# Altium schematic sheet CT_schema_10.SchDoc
size 741 x 377 mm
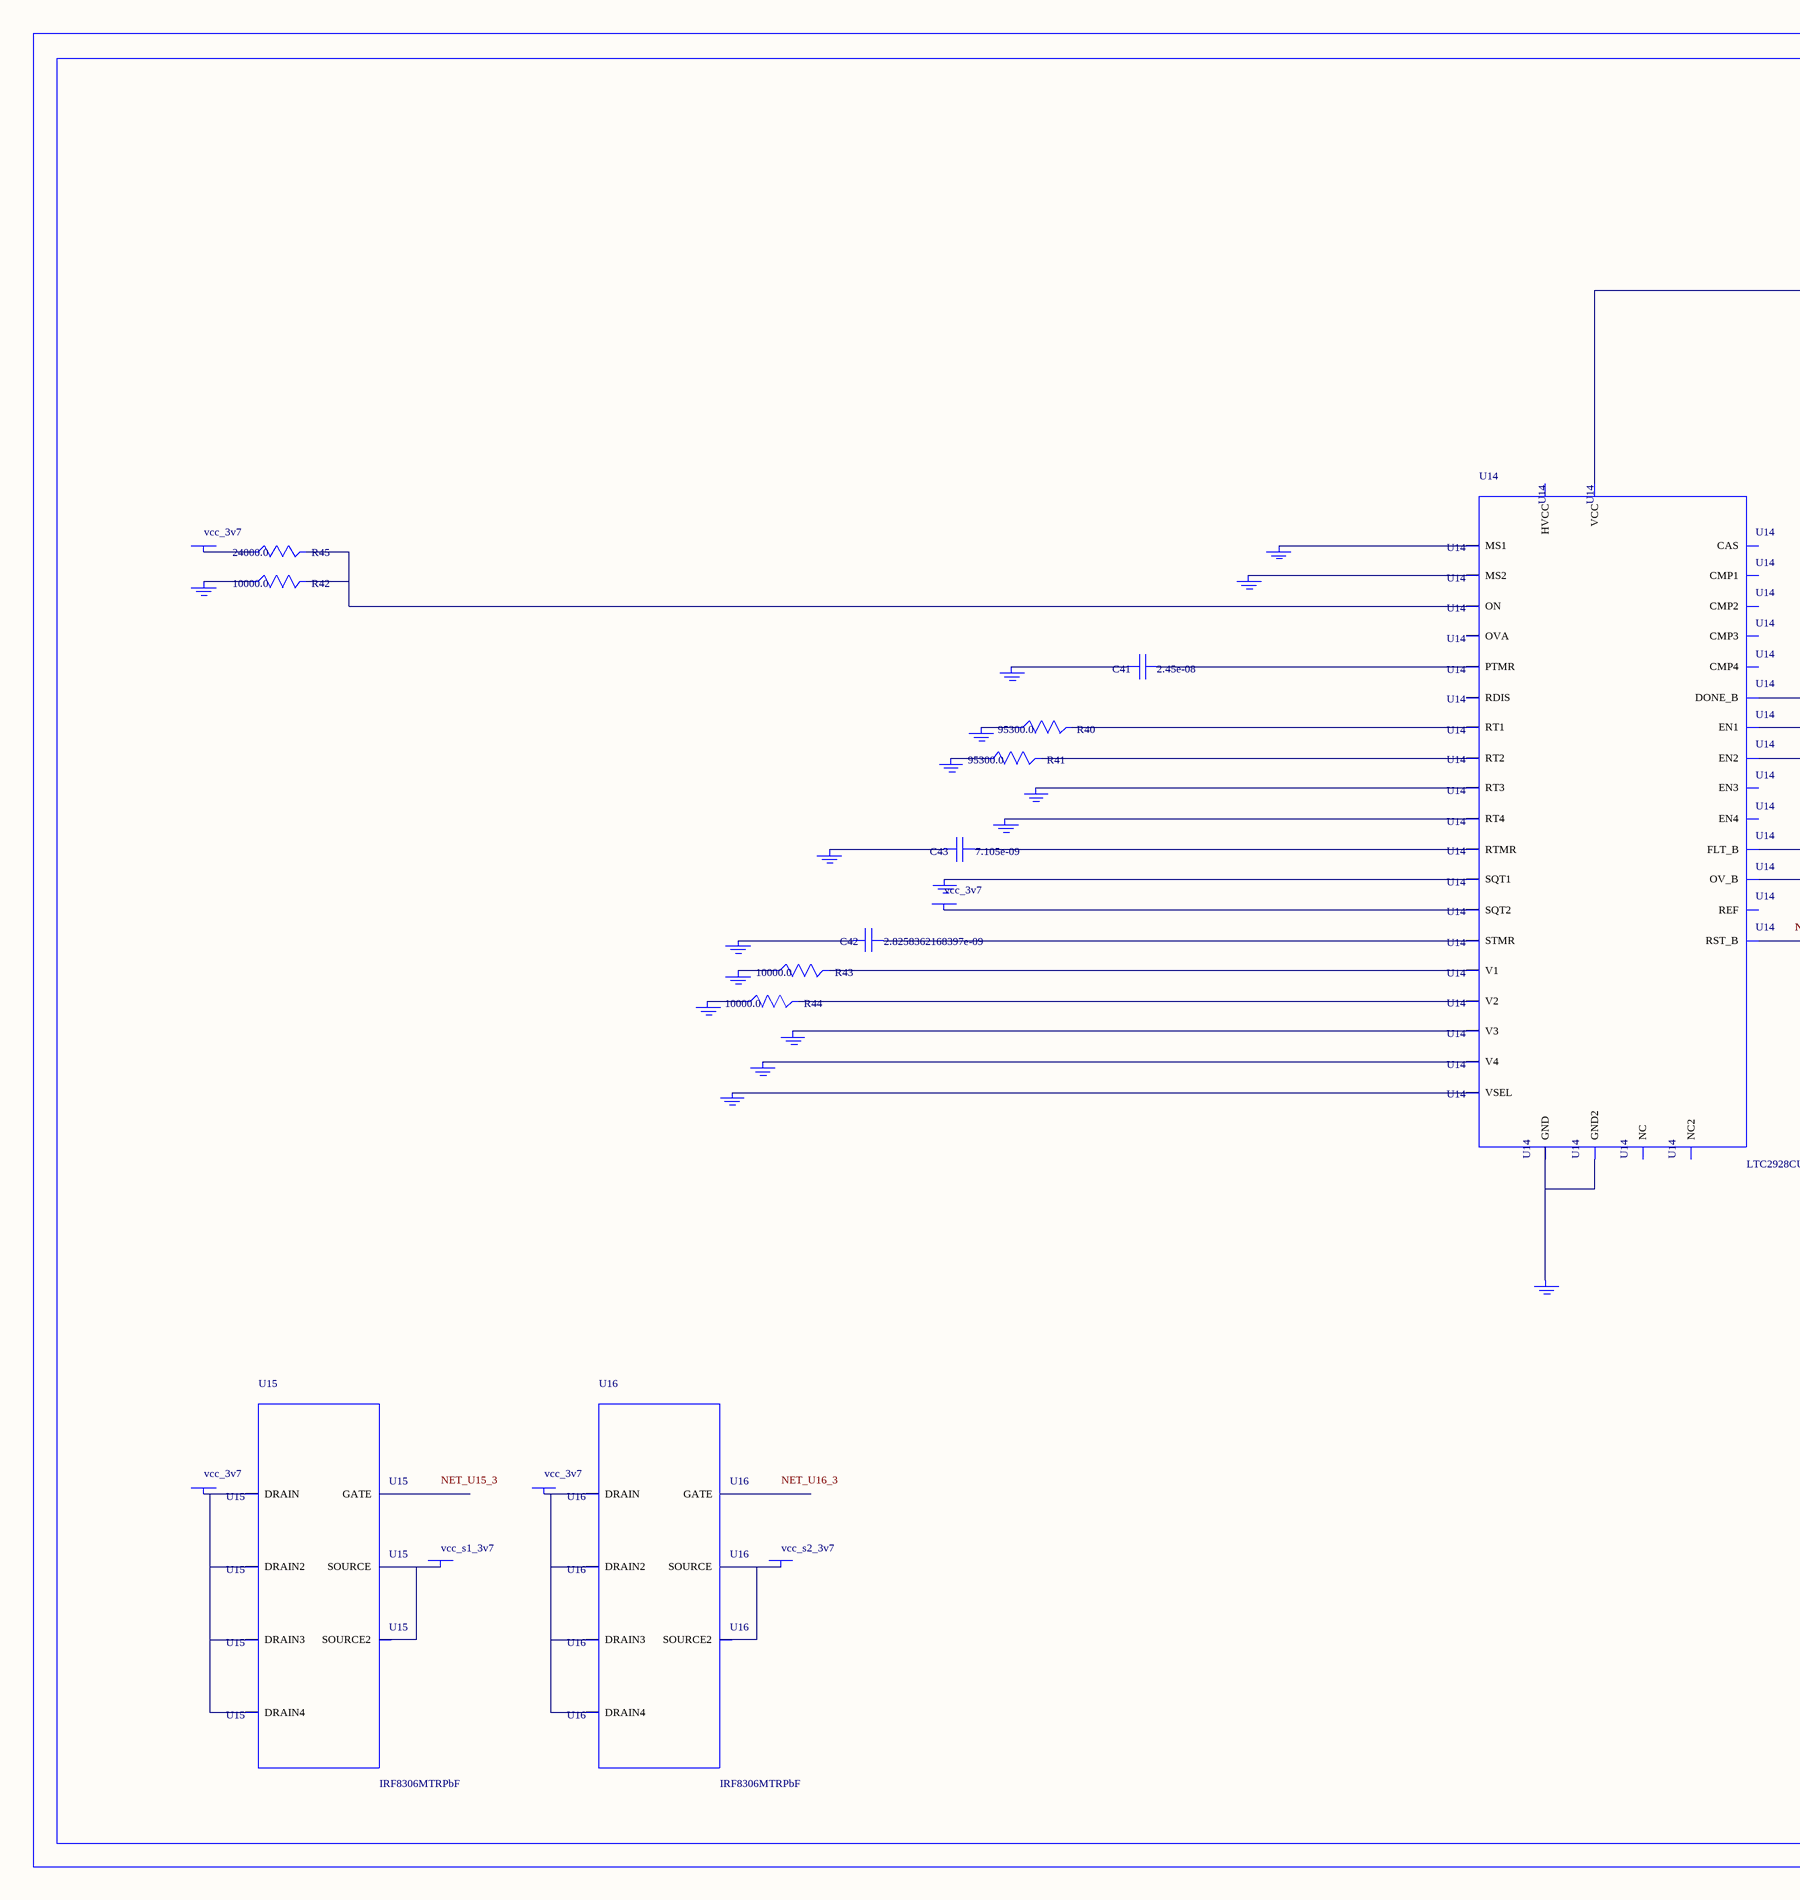
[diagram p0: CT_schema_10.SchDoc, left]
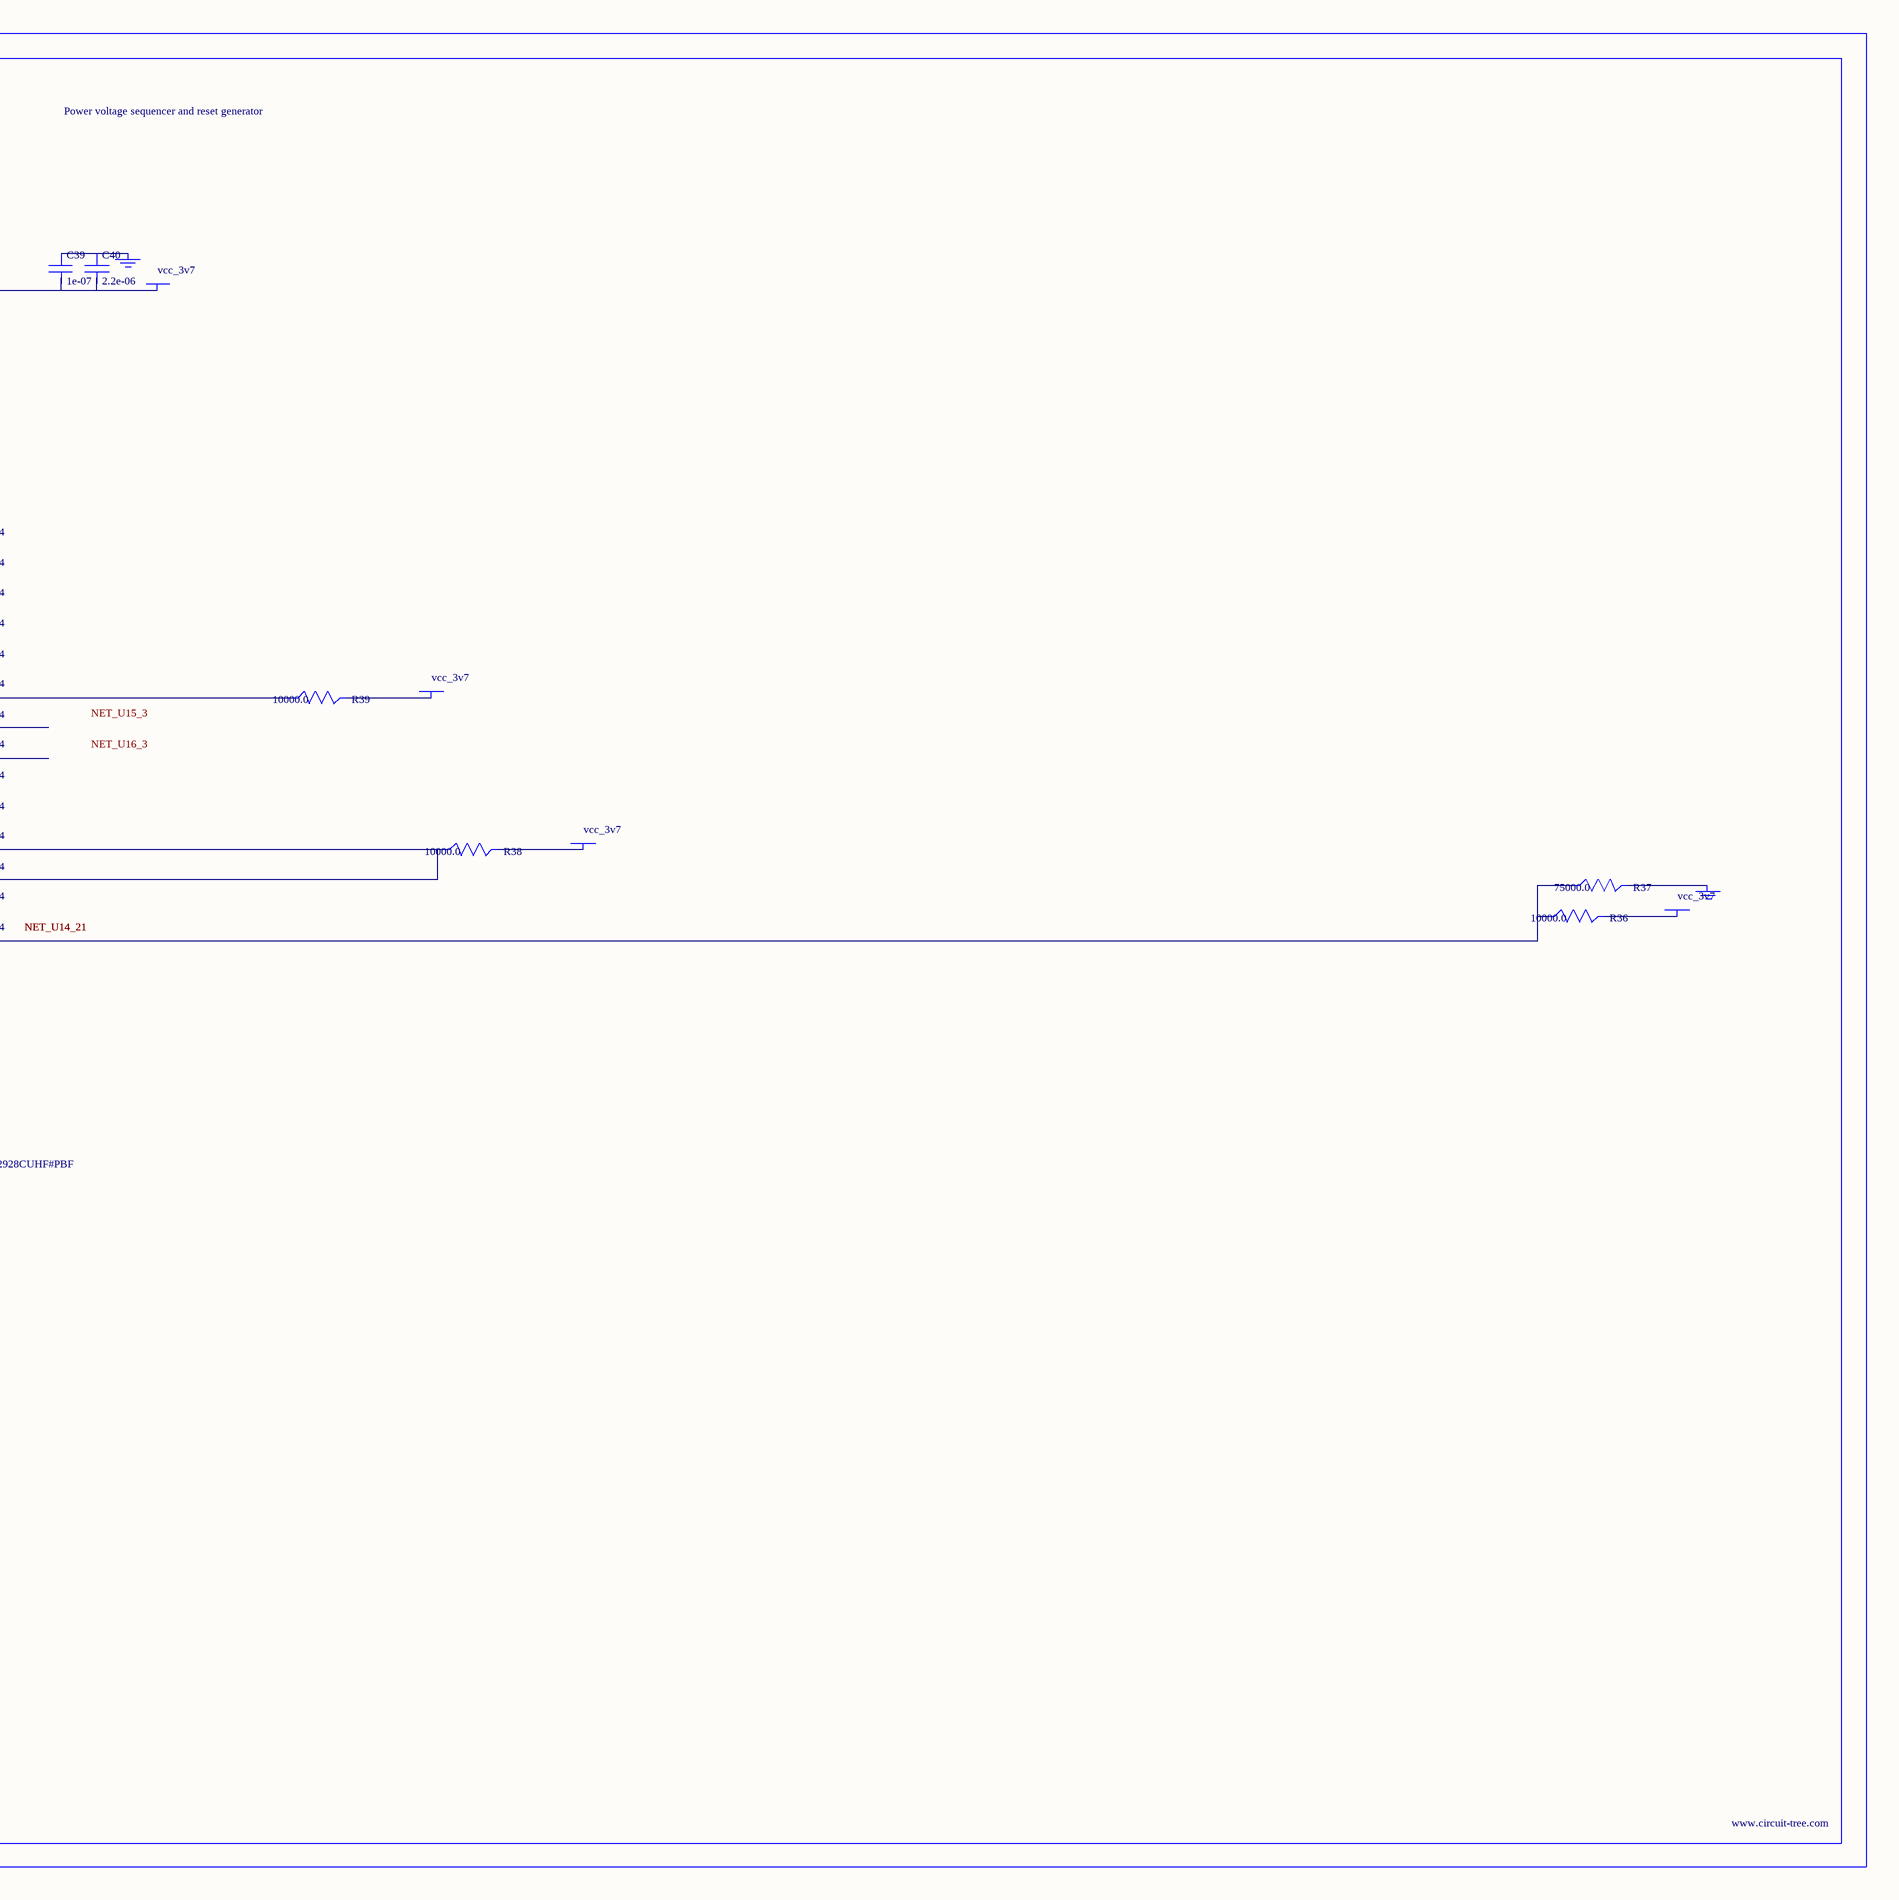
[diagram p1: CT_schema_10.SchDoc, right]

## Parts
BORDER9  (no value)
C39  1e-07  [C0402]
C40  2.2e-06  [C0603]
C41  2.45e-08  [R0603]
C42  2.8258362168397e-09  [R0603]
C43  7.105e-09  [R0603]
GND_INSTANCE_9_0  (no value)
GND_INSTANCE_9_1  (no value)
GND_INSTANCE_9_2  (no value)
GND_INSTANCE_9_3  (no value)
GND_INSTANCE_9_4  (no value)
GND_INSTANCE_9_5  (no value)
GND_INSTANCE_9_6  (no value)
GND_INSTANCE_9_7  (no value)
GND_INSTANCE_9_8  (no value)
GND_INSTANCE_9_9  (no value)
GND_INSTANCE_9_10  (no value)
GND_INSTANCE_9_11  (no value)
GND_INSTANCE_9_12  (no value)
GND_INSTANCE_9_13  (no value)
GND_INSTANCE_9_14  (no value)
GND_INSTANCE_9_15  (no value)
GND_INSTANCE_9_16  (no value)
GND_INSTANCE_9_17  (no value)
GND_INSTANCE_9_18  (no value)
POWER_INSTANCE_9_0  vcc_3v7
POWER_INSTANCE_9_1  vcc_3v7
POWER_INSTANCE_9_2  vcc_3v7
POWER_INSTANCE_9_3  vcc_3v7
POWER_INSTANCE_9_4  vcc_3v7
POWER_INSTANCE_9_5  vcc_3v7
POWER_INSTANCE_9_6  vcc_3v7
POWER_INSTANCE_9_7  vcc_s1_3v7
POWER_INSTANCE_9_8  vcc_3v7
POWER_INSTANCE_9_9  vcc_s2_3v7
R36  10000.0  [R0603]
R37  75000.0  [R0603]
R38  10000.0  [R0603]
R39  10000.0  [R0603]
R40  95300.0  [R0603]
R41  95300.0  [R0603]
R42  10000.0  [R0603]
R43  10000.0  [R0603]
R44  10000.0  [R0603]
R45  24000.0  [R0603]
U14  LTC2928CUHF#PBF  [QFN-38_UHF]
U15  IRF8306MTRPbF  [IRF8306MTRPBF]
U16  IRF8306MTRPbF  [IRF8306MTRPBF]

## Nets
NetC39_1: C39.1 C40.1 GND_INSTANCE_9_10.0(GND)
NetC39_2: C39.2 C40.2 POWER_INSTANCE_9_5.0(PWR) U14.22(VCC)
NetC41_1: C41.1 U14.27(PTMR)
NetC41_2: C41.2 GND_INSTANCE_9_13.0(GND)
NetC42_1: C42.1 U14.26(STMR)
NetC42_2: C42.2 GND_INSTANCE_9_12.0(GND)
NetC43_1: C43.1 U14.28(RTMR)
NetC43_2: C43.2 GND_INSTANCE_9_14.0(GND)
NetGND_INSTANCE_9_0_0: GND_INSTANCE_9_0.0(GND) R43.1
NetGND_INSTANCE_9_1_0: GND_INSTANCE_9_1.0(GND) R40.1
NetGND_INSTANCE_9_2_0: GND_INSTANCE_9_2.0(GND) R41.1
NetGND_INSTANCE_9_3_0: GND_INSTANCE_9_3.0(GND) U14.8(RT3)
NetGND_INSTANCE_9_4_0: GND_INSTANCE_9_4.0(GND) U14.9(RT4)
NetGND_INSTANCE_9_5_0: GND_INSTANCE_9_5.0(GND) U14.10(SQT1)
NetGND_INSTANCE_9_6_0: GND_INSTANCE_9_6.0(GND) U14.12(MS1)
NetGND_INSTANCE_9_7_0: GND_INSTANCE_9_7.0(GND) U14.13(MS2)
NetGND_INSTANCE_9_8_0: GND_INSTANCE_9_8.0(GND) R42.1
NetGND_INSTANCE_9_9_0: GND_INSTANCE_9_9.0(GND) R37.2
NetGND_INSTANCE_9_11_0: GND_INSTANCE_9_11.0(GND) U14.25(VSEL)
NetGND_INSTANCE_9_15_0: GND_INSTANCE_9_15.0(GND) U14.30(V4)
NetGND_INSTANCE_9_16_0: GND_INSTANCE_9_16.0(GND) U14.32(V3)
NetGND_INSTANCE_9_17_0: GND_INSTANCE_9_17.0(GND) R44.1
NetGND_INSTANCE_9_18_0: GND_INSTANCE_9_18.0(GND) U14.24(GND) U14.39(GND2)
NetPOWER_INSTANCE_9_0_0: POWER_INSTANCE_9_0.0(PWR) U14.11(SQT2)
NetPOWER_INSTANCE_9_1_0: POWER_INSTANCE_9_1.0(PWR) R45.1
NetPOWER_INSTANCE_9_2_0: POWER_INSTANCE_9_2.0(PWR) R39.2
NetPOWER_INSTANCE_9_3_0: POWER_INSTANCE_9_3.0(PWR) R38.2
NetPOWER_INSTANCE_9_4_0: POWER_INSTANCE_9_4.0(PWR) R36.2
NetPOWER_INSTANCE_9_6_0: POWER_INSTANCE_9_6.0(PWR) U15.1(DRAIN) U15.2(DRAIN2) U15.6(DRAIN3) U15.7(DRAIN4)
NetPOWER_INSTANCE_9_7_0: POWER_INSTANCE_9_7.0(PWR) U15.4(SOURCE) U15.5(SOURCE2)
NetPOWER_INSTANCE_9_8_0: POWER_INSTANCE_9_8.0(PWR) U16.1(DRAIN) U16.2(DRAIN2) U16.6(DRAIN3) U16.7(DRAIN4)
NetPOWER_INSTANCE_9_9_0: POWER_INSTANCE_9_9.0(PWR) U16.4(SOURCE) U16.5(SOURCE2)
NetR36_1: R36.1 R37.1 U14.21(RST_B)
NetR38_1: R38.1 U14.19(FLT_B) U14.20(OV_B)
NetR39_1: R39.1 U14.18(DONE_B)
NetR40_2: R40.2 U14.6(RT1)
NetR41_2: R41.2 U14.7(RT2)
NetR42_2: R42.2 R45.2 U14.16(ON)
NetR43_2: R43.2 U14.3(V1)
NetR44_2: R44.2 U14.38(V2)

Not connected (* = marked no-connect by the designer): U14 1(OVA) 2(EN1) 4(NC) 5(REF) 14(RDIS) 15(CAS) 17(NC2) 23(HVCC) 29(EN4) 31(EN3) 33(CMP3) 34(CMP4) 35(CMP1) 36(CMP2) 37(EN2); U15 3(GATE); U16 3(GATE)

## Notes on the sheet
- Labels drawn without touching a wire or pin: NET_U15_3, NET_U16_3

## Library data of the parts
BORDER9 = BORDER_PAGE9
C39 = C0402C104K3RACTU
C40 = GRM188R61H225KE1115D
C41 = C41
C42 = C42
C43 = C43
GND_INSTANCE_9_0-GND_INSTANCE_9_18 = GND
POWER_INSTANCE_9_0-POWER_INSTANCE_9_9 = PWR
R36 R38 R39 R42-R44 = RC0603JR-0710KL
R37 = RC0603JR-0775KL
R40 R41 = RC0603FR-0795K3L
R45 = RC0603JR-0724KL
